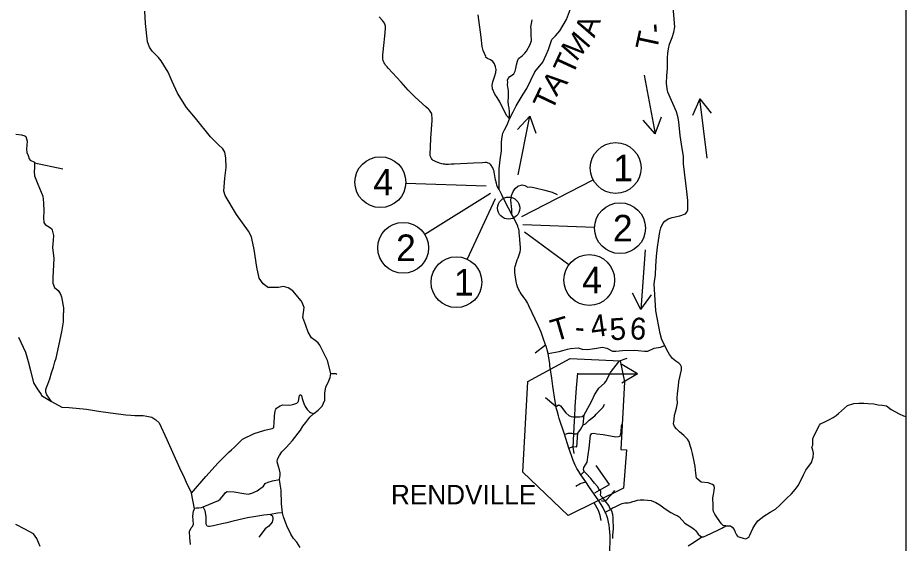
# Model space of a CAD drawing. Extents: x 2025369 to 2161369, y 549489 to 637489.
# Drawn here: x 2069680 to 2092420, y 587393 to 600839 of the extents above; entities that cross this region are included whole.
import ezdxf

# ---------------------------------------------------------------- set-up
doc = ezdxf.new("R2010")
doc.units = 0
for name, color, linetype in [('GM_X_City_Street', 7, 'Continuous'), ('GM_X_Corporation', 7, 'Continuous'), ('GM_X_Corporation_Text', 7, 'Continuous'), ('GM_X_County_Road', 7, 'Continuous'), ('GM_X_State_Route', 7, 'Continuous'), ('GM_X_Township_Road', 7, 'Continuous'), ('GM_X_Township_Road_Text', 7, 'Continuous'), ('GM_X_Township_Subdivision', 7, 'Continuous'), ('SH_Text', 7, 'Continuous')]:
    doc.layers.add(name, color=color, linetype=linetype)

msp = doc.modelspace()

# ---------------------------------------------------------------- linework, layer by layer
at = {"layer": 'GM_X_City_Street'}
for points in [[(2084379, 591057), (2084444, 591194), (2084551, 591359), (2084700, 591492), (2084728, 591531), (2084851, 591759), (2085081, 592061), (2085274, 592130)], [(2083929, 590522), (2083934, 590630), (2083947, 590885), (2083980, 591373), (2084014, 591745)], [(2083189, 591120), (2083237, 591080), (2083457, 590893), (2083516, 590935), (2083547, 590927), (2083575, 590910), (2083709, 590732), (2083783, 590661), (2083841, 590634), (2083891, 590629), (2083934, 590630), (2084031, 590626), (2084064, 590626), (2084127, 590637), (2084176, 590676), (2084317, 590926), (2084379, 591057)], [(2084487, 590696), (2084662, 590878), (2084700, 590953)], [(2084011, 590210), (2084041, 590245), (2084080, 590299), (2084154, 590421), (2084154, 590426), (2084176, 590676)], [(2084154, 590426), (2084209, 590451), (2084306, 590543), (2084450, 590657), (2084487, 590696)], [(2083903, 590033), (2083914, 590195), (2083929, 590522)], [(2084179, 589229), (2084163, 589280), (2084171, 589335), (2084257, 589467), (2084277, 589655), (2084303, 589825), (2084343, 590154), (2084373, 590198), (2084426, 590207), (2084502, 590190), (2084666, 590171), (2084986, 590113), (2085055, 590122), (2085096, 590136), (2085123, 590235), (2085135, 590394), (2085156, 590440)], [(2083670, 590180), (2083722, 590195), (2083745, 590201), (2083766, 590206), (2083787, 590208), (2083809, 590208), (2083849, 590206), (2083914, 590195)], [(2083914, 590195), (2083978, 590189), (2084011, 590210)], [(2083990, 589860), (2084011, 590210)], [(2083924, 589687), (2083898, 589854), (2083893, 589870), (2083900, 589979), (2083903, 590033)], [(2083785, 589825), (2083893, 589870), (2083990, 589860)], [(2084716, 588477), (2084671, 588525), (2084645, 588559), (2084604, 588607), (2084595, 588643), (2084602, 588677), (2084600, 588727), (2084569, 588750), (2084520, 588841), (2084440, 588929), (2084347, 589050), (2084228, 589174), (2084179, 589229), (2084094, 589144)], [(2084827, 588894), (2084480, 589384)], [(2083975, 588843), (2083985, 588874), (2084037, 588895), (2084076, 588921), (2084218, 588968)], [(2084447, 588682), (2084569, 588750), (2084827, 588894)]]:
    msp.add_lwpolyline(points, dxfattribs=at)
at = {"layer": 'GM_X_Corporation'}
msp.add_lwpolyline([(2085095, 592063), (2085208, 591523), (2085114, 589792), (2085263, 589786), (2085181, 588800), (2083764, 588099), (2082608, 589214), (2082739, 591530), (2083821, 592119)], close=True, dxfattribs=at)
at = {"layer": 'GM_X_County_Road'}
for points in [[(2081997, 596444), (2082001, 596772), (2082004, 596977), (2082029, 597206), (2082060, 597434), (2082064, 597665), (2082077, 597794), (2082097, 597883), (2082139, 597975), (2082202, 598097), (2082267, 598249), (2082359, 598434), (2082440, 598583), (2082619, 598884), (2082706, 599025), (2082910, 599453), (2083120, 599704), (2083203, 599887), (2083268, 600028), (2083322, 600208), (2083347, 600281), (2083441, 600376), (2083556, 600508), (2083722, 600793), (2083875, 601207)], [(2076938, 593585), (2076928, 593601), (2076810, 593744), (2076716, 593855), (2076597, 593932), (2076483, 593963), (2076357, 593939), (2076099, 593939), (2076096, 593929), (2075959, 594034), (2075862, 594175), (2075798, 594455), (2075733, 594906), (2075671, 595188), (2075658, 595237), (2075583, 595379), (2075282, 595809), (2074991, 596290), (2074955, 596406), (2074981, 596734), (2075018, 597010), (2075009, 597259), (2074982, 597401), (2074929, 597486), (2074809, 597597), (2074613, 597788), (2074227, 598272), (2074002, 598545), (2073769, 598912), (2073628, 599209), (2073532, 599443), (2073421, 599622), (2073351, 599739), (2073285, 599821), (2073194, 599908), (2073123, 599986), (2073054, 600090), (2073004, 600226), (2072952, 600690), (2072932, 601007)], [(2069627, 597861), (2069777, 597840), (2069861, 597820), (2069885, 597798), (2069918, 597678), (2069907, 597476), (2069915, 597389), (2069948, 597317), (2069970, 597231), (2070000, 597193), (2070110, 597144), (2070109, 597128), (2070107, 597100), (2070107, 596998), (2070099, 596904), (2070110, 596790), (2070191, 596579), (2070320, 596275), (2070339, 596106), (2070346, 595890), (2070341, 595716), (2070345, 595600), (2070385, 595546), (2070452, 595509), (2070546, 595447), (2070558, 595405)], [(2070558, 595405), (2070576, 595338), (2070595, 595271), (2070589, 595152), (2070572, 594958), (2070601, 594676), (2070574, 594195), (2070577, 594047), (2070620, 593937), (2070712, 593860), (2070765, 593785), (2070796, 593700), (2070850, 593419), (2070853, 593289)], [(2076905, 587280), (2076826, 587416), (2076738, 587514), (2076667, 587625), (2076568, 587841), (2076485, 588068), (2076459, 588171), (2076426, 588397), (2076418, 588748), (2076398, 588902), (2076377, 589023), (2076393, 589125), (2076392, 589197), (2076378, 589267), (2076352, 589353), (2076335, 589416), (2076319, 589480), (2076325, 589544), (2076376, 589634), (2076438, 589730), (2076549, 589842), (2076709, 590019), (2076919, 590289), (2076980, 590391), (2077057, 590482), (2077155, 590619), (2077254, 590715), (2077367, 590800), (2077469, 590901), (2077539, 591058), (2077539, 591230), (2077562, 591396), (2077625, 591509), (2077676, 591632), (2077696, 591737), (2077607, 592069), (2077412, 592463), (2077367, 592518), (2077290, 592578), (2077200, 592651), (2077113, 592793), (2077049, 592963), (2076980, 593169), (2077008, 593423), (2076980, 593514), (2076938, 593585)], [(2088114, 587568), (2088160, 587551), (2088246, 587519), (2088312, 587506), (2088394, 587551), (2088419, 587601), (2088492, 587769), (2088543, 587851), (2088625, 587962), (2088774, 588082), (2088935, 588190), (2089074, 588262), (2089182, 588369), (2089353, 588535), (2089480, 588653), (2089578, 588771), (2089661, 588881), (2089792, 589141), (2089851, 589263), (2089993, 589455), (2090036, 589593), (2090045, 589695), (2090027, 589777), (2090007, 589849), (2090028, 589905), (2090028, 589985), (2090030, 590066), (2090059, 590134), (2090198, 590416), (2090228, 590444), (2090352, 590509), (2090453, 590561), (2090547, 590609), (2090625, 590659), (2090690, 590712), (2090844, 590846), (2090921, 590918), (2091079, 590966), (2091203, 590979), (2091335, 590977), (2091449, 590970), (2091589, 590956), (2091705, 590935), (2091801, 590923), (2091919, 590906), (2092037, 590812), (2092241, 590705), (2092346, 590650), (2092420, 590640)], [(2074102, 587360), (2074085, 587539), (2074072, 587697), (2074118, 587787), (2074152, 587823), (2074175, 587881), (2074157, 588087), (2074176, 588210), (2074205, 588270), (2074212, 588286), (2074251, 588300), (2074317, 588299), (2074379, 588311), (2074427, 588325), (2074820, 588490), (2074858, 588524), (2074950, 588629), (2074995, 588691), (2075037, 588717), (2075219, 588707), (2075413, 588672), (2075575, 588651), (2075667, 588675), (2075805, 588736), (2075968, 588852), (2076012, 588920), (2076088, 588958), (2076199, 588993), (2076377, 589023)], [(2084714, 588192), (2084847, 588254), (2084900, 588296), (2084952, 588320), (2085035, 588361), (2085104, 588396), (2085150, 588409), (2085221, 588425), (2085255, 588428), (2085303, 588425), (2085355, 588431), (2085424, 588458), (2085462, 588473), (2085539, 588493), (2085614, 588507), (2085706, 588507), (2085795, 588498), (2085888, 588488), (2086012, 588436), (2086112, 588377), (2086250, 588277), (2086394, 588177), (2086507, 588117), (2086556, 588101), (2086610, 588066), (2086752, 587908), (2086932, 587792), (2086999, 587740), (2087036, 587711), (2087096, 587628), (2087156, 587574), (2087192, 587553), (2087230, 587555), (2087308, 587590), (2087585, 587721), (2087697, 587782), (2087801, 587834), (2087866, 587842), (2087925, 587834), (2087963, 587805), (2088015, 587747), (2088040, 587680), (2088072, 587608), (2088100, 587573), (2088114, 587568)]]:
    msp.add_lwpolyline(points, dxfattribs=at)
at = {"layer": 'GM_X_State_Route'}
for points in [[(2083295, 591995), (2083275, 592139), (2083257, 592245), (2083231, 592345), (2083211, 592409), (2083189, 592470), (2083131, 592639), (2083076, 592795), (2083043, 592874), (2083003, 592964), (2082847, 593291), (2082763, 593470), (2082743, 593509), (2082727, 593543), (2082703, 593588), (2082675, 593630), (2082636, 593685), (2082597, 593733), (2082565, 593778), (2082542, 593814), (2082520, 593853), (2082499, 593895), (2082474, 593950), (2082454, 594011), (2082443, 594051), (2082426, 594140), (2082409, 594264), (2082403, 594324), (2082399, 594369), (2082402, 594411), (2082405, 594439), (2082411, 594473), (2082418, 594503), (2082466, 594642), (2082487, 594695), (2082505, 594746), (2082523, 594801), (2082536, 594851), (2082544, 594899), (2082547, 594948), (2082532, 595164), (2082522, 595270), (2082517, 595334), (2082510, 595386), (2082502, 595429), (2082491, 595466), (2082477, 595509), (2082459, 595551), (2082430, 595610), (2082365, 595733), (2082329, 595804), (2082158, 596129), (2082067, 596304), (2081997, 596444), (2081973, 596491), (2081961, 596517), (2081945, 596559), (2081931, 596607), (2081911, 596694), (2081886, 596843), (2081877, 596884), (2081870, 596911), (2081859, 596946), (2081846, 596977), (2081835, 597003), (2081817, 597035), (2081806, 597053), (2081789, 597075), (2081771, 597091), (2081750, 597107), (2081723, 597121), (2081701, 597128), (2081677, 597132), (2081645, 597133), (2081573, 597131), (2081347, 597120), (2080851, 597095), (2080769, 597091), (2080708, 597088), (2080676, 597087), (2080640, 597086), (2080607, 597089), (2080572, 597095), (2080531, 597103), (2080478, 597120), (2080368, 597162), (2080335, 597178), (2080315, 597189), (2080288, 597212), (2080266, 597238), (2080249, 597269), (2080238, 597305), (2080234, 597330), (2080232, 597361), (2080242, 597524), (2080256, 597762), (2080283, 598208), (2080284, 598283), (2080279, 598340), (2080274, 598368), (2080266, 598395), (2080252, 598426), (2080236, 598452), (2080215, 598478), (2080190, 598503), (2080127, 598561), (2079852, 598804), (2079762, 598889), (2079721, 598931), (2079668, 598988), (2079492, 599187), (2079273, 599429), (2079164, 599549), (2079133, 599581), (2079115, 599602), (2079094, 599628), (2079075, 599656), (2079055, 599689), (2079041, 599723), (2079033, 599747), (2079026, 599777), (2079022, 599817), (2079022, 599850), (2079025, 599894), (2079032, 599963), (2079050, 600132), (2079075, 600367), (2079093, 600563), (2079093, 600599), (2079091, 600624), (2079086, 600652), (2079078, 600676), (2079065, 600702), (2079045, 600732), (2079013, 600770), (2078932, 600861)], [(2083302, 591945), (2083299, 591972), (2083295, 591995)], [(2084613, 588384), (2084551, 588480), (2084479, 588585), (2084317, 588821), (2084218, 588968), (2084094, 589144), (2084038, 589231), (2083993, 589308), (2083950, 589390), (2083924, 589447), (2083898, 589506), (2083858, 589612), (2083815, 589733), (2083785, 589825), (2083670, 590180), (2083539, 590581), (2083518, 590649), (2083482, 590777), (2083463, 590858), (2083457, 590893), (2083433, 591023), (2083377, 591410), (2083348, 591616), (2083302, 591945)], [(2084836, 586929), (2084837, 587191), (2084841, 587479), (2084841, 587586), (2084837, 587678), (2084829, 587773), (2084818, 587851), (2084818, 587856), (2084801, 587932), (2084780, 588014), (2084753, 588098), (2084728, 588159), (2084714, 588192), (2084663, 588297), (2084615, 588381), (2084613, 588384)]]:
    msp.add_lwpolyline(points, dxfattribs=at)
at = {"layer": 'GM_X_Township_Road'}
for points in [[(2086634, 597825), (2086613, 598007), (2086600, 598168), (2086586, 598282), (2086542, 598432), (2086317, 598932), (2086299, 599019), (2086286, 599169), (2086292, 599350), (2086310, 599542), (2086314, 599684), (2086313, 599814), (2086319, 599936), (2086336, 600042), (2086362, 600166), (2086427, 600331), (2086472, 600471), (2086495, 600610), (2086433, 601415)], [(2082267, 598249), (2082199, 598330), (2082088, 598547), (2082020, 598690), (2081951, 598797), (2081889, 598884), (2081832, 599020), (2081826, 599111), (2081840, 599201), (2081893, 599349), (2081914, 599441), (2081922, 599511), (2081906, 599580), (2081878, 599659), (2081838, 599723), (2081783, 599761), (2081704, 599800), (2081653, 599829), (2081656, 599844), (2081592, 600005), (2081568, 600106), (2081540, 600340), (2081461, 600915)], [(2082267, 598249), (2082264, 598431), (2082258, 598532), (2082237, 598604), (2082231, 598696), (2082243, 598812), (2082240, 598973), (2082217, 599119), (2082223, 599192), (2082215, 599241), (2082235, 599282), (2082276, 599332), (2082340, 599378), (2082373, 599408), (2082408, 599469), (2082429, 599543), (2082448, 599633), (2082469, 599729), (2082499, 599793), (2082590, 599866), (2082657, 599932), (2082699, 599983), (2082796, 600155), (2082826, 600261), (2082820, 600410), (2082823, 600501), (2082817, 600535), (2082809, 600596), (2082849, 600790)], [(2086238, 592454), (2086167, 592600), (2086119, 592761), (2086011, 593343), (2085969, 594028), (2086002, 594264), (2086008, 594486), (2086029, 594738), (2086054, 594968), (2086077, 595136), (2086114, 595362), (2086142, 595466), (2086192, 595577), (2086245, 595636), (2086323, 595693), (2086427, 595731), (2086626, 595769), (2086767, 595818), (2086804, 595866), (2086827, 595926), (2086834, 596164), (2086807, 596391), (2086715, 597104), (2086717, 597288), (2086665, 597601), (2086647, 597714), (2086634, 597825)], [(2070109, 597128), (2070830, 596972)], [(2082329, 595804), (2082326, 595931), (2082298, 596171), (2082320, 596291), (2082356, 596392), (2082409, 596472), (2082478, 596534), (2082589, 596561), (2082659, 596549), (2082731, 596506), (2082803, 596510), (2082887, 596496), (2083167, 596428), (2083354, 596373), (2083484, 596313)], [(2070539, 591018), (2070428, 591194), (2070401, 591256), (2070401, 591328), (2070414, 591382), (2070450, 591467), (2070504, 591601), (2070544, 591754), (2070593, 591902), (2070629, 592036), (2070661, 592131), (2070806, 592805), (2070848, 593057), (2070854, 593149), (2070853, 593289)], [(2069702, 592668), (2069875, 592279), (2069950, 592044), (2070004, 591813), (2070083, 591495), (2070192, 591322), (2070200, 591309), (2070277, 591196)], [(2082923, 592264), (2083189, 592470)], [(2083257, 592245), (2083537, 592300), (2083633, 592323), (2083747, 592356), (2083823, 592377), (2084020, 592392), (2084125, 592359), (2084266, 592347), (2084500, 592388), (2084641, 592408), (2084758, 592388), (2084900, 592311), (2084985, 592311), (2085162, 592323), (2085469, 592331), (2085558, 592323), (2085719, 592311), (2085806, 592311), (2085969, 592384), (2086129, 592412), (2086238, 592454)], [(2087801, 587834), (2087738, 587849), (2087695, 587886), (2087588, 588036), (2087522, 588140), (2087491, 588208), (2087477, 588248), (2087476, 588359), (2087471, 588556), (2087487, 588639), (2087506, 588743), (2087512, 588819), (2087493, 588866), (2087461, 588895), (2087351, 588936), (2087168, 588953), (2087117, 588994), (2087055, 589056), (2087032, 589186), (2087014, 589353), (2086981, 589528), (2086951, 589689), (2086922, 589792), (2086891, 589896), (2086861, 589988), (2086820, 590059), (2086727, 590152), (2086615, 590244), (2086543, 590316), (2086492, 590377), (2086461, 590449), (2086482, 590561), (2086492, 590674), (2086512, 590756), (2086543, 590848), (2086563, 590981), (2086553, 591104), (2086563, 591227), (2086594, 591422), (2086601, 591534), (2086668, 591834), (2086664, 591905), (2086646, 591960), (2086601, 592004), (2086522, 592048), (2086436, 592123), (2086357, 592226), (2086294, 592341), (2086238, 592454)], [(2077696, 591737), (2077823, 591733), (2077843, 591721)], [(2070277, 591196), (2070291, 591175), (2070539, 591018), (2070808, 590877), (2070996, 590864), (2071437, 590820), (2071746, 590776), (2072054, 590731), (2072450, 590679), (2072578, 590669), (2072672, 590665), (2072892, 590665), (2072987, 590644), (2073113, 590621), (2073210, 590552), (2073296, 590475), (2073495, 590050), (2073819, 589320), (2073935, 589076), (2073994, 588952)], [(2076232, 590368), (2076236, 590385), (2076246, 590460), (2076252, 590653), (2076266, 590776), (2076276, 590808), (2076284, 590827), (2076299, 590845), (2076355, 590886), (2076396, 590910), (2076436, 590928), (2076463, 590932), (2076641, 590930), (2076721, 590947), (2076820, 590979), (2076852, 590999), (2076858, 591009), (2076867, 591027), (2076888, 591173), (2076901, 591188), (2076907, 591190), (2076921, 591190), (2076929, 591185), (2076939, 591171), (2076955, 591094), (2077002, 590969), (2077037, 590893), (2077091, 590817), (2077150, 590751), (2077170, 590735), (2077192, 590727), (2077221, 590717), (2077254, 590715)], [(2075152, 589780), (2075230, 589849), (2075436, 590052), (2075729, 590197), (2076007, 590282), (2076192, 590332), (2076207, 590336), (2076222, 590348), (2076230, 590358), (2076232, 590368)], [(2073994, 588952), (2074127, 588673), (2074493, 589097), (2074811, 589452), (2075031, 589673), (2075085, 589720), (2075152, 589780)], [(2074205, 588270), (2074127, 588673)], [(2084806, 588362), (2084716, 588477)], [(2084908, 587510), (2084914, 587593), (2084924, 587774), (2084920, 588006), (2084921, 588047), (2084909, 588132), (2084885, 588210), (2084869, 588246), (2084847, 588254), (2084825, 588317), (2084820, 588344), (2084806, 588362)], [(2070256, 587313), (2070171, 587514), (2070086, 587633), (2069859, 587754), (2069630, 587869)], [(2086842, 587329), (2087004, 587430), (2087192, 587553)]]:
    msp.add_lwpolyline(points, dxfattribs=at)
at = {"layer": 'GM_X_Township_Subdivision'}
for points in [[(2084616, 588488), (2084667, 588471), (2084716, 588477), (2084764, 588520), (2084837, 588596), (2084883, 588645), (2084958, 588741)], [(2076459, 588171), (2076328, 588161), (2076152, 588132), (2075975, 588111), (2075777, 588078), (2075563, 588046), (2075340, 587992), (2075158, 587953), (2075027, 587919), (2074899, 587887), (2074762, 587851), (2074686, 587835), (2074590, 587818), (2074562, 587817), (2074530, 587831), (2074505, 587877), (2074500, 587953), (2074502, 588069), (2074486, 588181), (2074476, 588221), (2074463, 588257), (2074427, 588325)], [(2084612, 587976), (2084587, 588100), (2084544, 588232), (2084433, 588428)], [(2076152, 588132), (2076199, 588091), (2076210, 588013), (2076193, 587932), (2076105, 587828), (2076016, 587759), (2075849, 587552)]]:
    msp.add_lwpolyline(points, dxfattribs=at)
at = {"layer": 'SH_Text'}
for p, q in [((2085714, 599370), (2085998, 597866)), ((2087141, 598768), (2086951, 598342)), ((2087326, 597249), (2087141, 598768)), ((2087141, 598768), (2087428, 598400)), ((2082782, 598324), (2082470, 597977)), ((2082490, 596822), (2082782, 598324)), ((2082782, 598324), (2082941, 597886)), ((2085998, 597866), (2086160, 598304)), ((2085998, 597866), (2085688, 598215)), ((2079610, 596610), (2081671, 596541)), ((2082583, 595751), (2084405, 596696)), ((2081778, 596340), (2080096, 595296)), ((2081898, 596206), (2081181, 594661)), ((2082609, 595545), (2084444, 595478)), ((2083785, 594515), (2082653, 595355)), ((2085740, 594897), (2085628, 593372)), ((2085628, 593372), (2085418, 593788)), ((2085628, 593372), (2085897, 593753)), ((2085544, 591728), (2085144, 591968)), ((2084014, 591728), (2085544, 591728)), ((2085544, 591728), (2085144, 591488))]:
    msp.add_line(p, q, dxfattribs=at)
msp.add_lwpolyline([(2037369, 631489), (2037369, 571561), (2092420, 571561), (2092420, 631489)], dxfattribs=at)
for centre, radius in [((2084982, 596995), 650), ((2078961, 596632), 650), ((2082244, 595967), 283), ((2085094, 595455), 650), ((2079544, 594953), 650), ((2080907, 594072), 650), ((2084307, 594128), 650)]:
    msp.add_circle(centre, radius, dxfattribs=at)

# ---------------------------------------------------------------- texts
at = {"layer": 'GM_X_Corporation_Text'}
msp.add_text('RENDVILLE', height=500, rotation=0, dxfattribs=at).set_placement((2079233, 588387))
at = {"layer": 'GM_X_Township_Road_Text'}
for s, rotation, p in [('A', 69.6849, (2084439, 600310)), ('-', 94.3978, (2086225, 600467)), ('M', 49.0315, (2083966, 599699)), ('T', 77.9094, (2086033, 599968)), ('T', 65.3145, (2083875, 599337)), ('A', 50.2305, (2083465, 598806)), ('T', 64.477, (2083351, 598426)), ('T', 16.3079, (2083416, 592551)), ('4', 8.1413, (2084380, 592653)), ('5', 3.8991, (2084848, 592582)), ('6', 355.7117, (2085332, 592621)), ('-', 355.102, (2083921, 592658))]:
    msp.add_text(s, height=560, rotation=rotation, dxfattribs=at).set_placement(p)
at = {"layer": 'SH_Text'}
for s, p in [('1', (2084920, 596655)), ('4', (2078779, 596292)), ('2', (2084912, 595115)), ('2', (2079362, 594613)), ('4', (2084125, 593788)), ('1', (2080845, 593732))]:
    msp.add_text(s, height=680, dxfattribs=at).set_placement(p)

doc.saveas('drawing.dxf')
